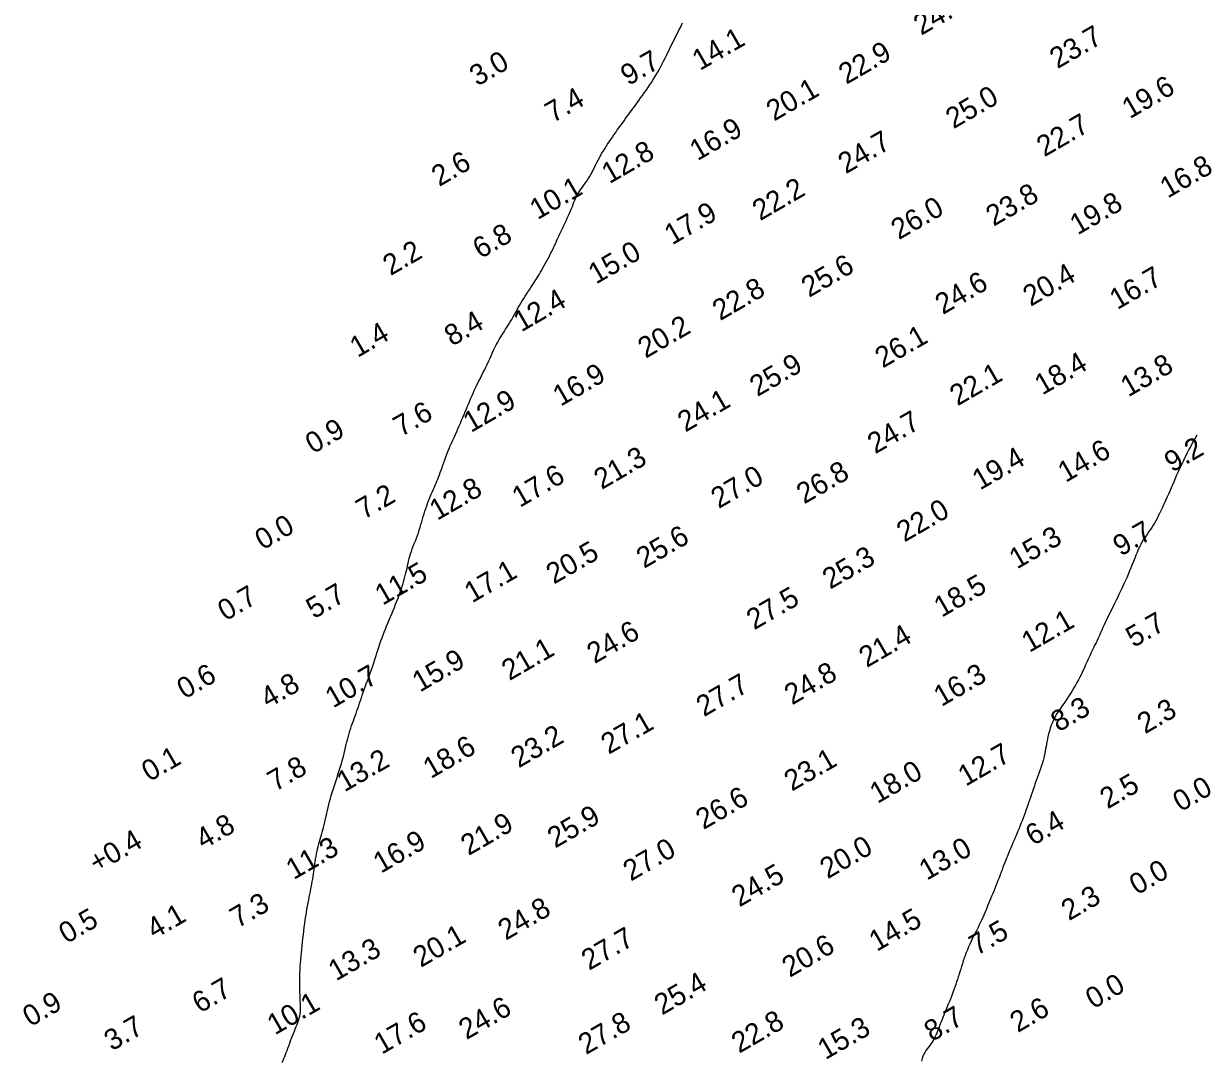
# Model space of a CAD drawing. Extents: x 3024098 to 3056816, y 418252 to 509144.
# Drawn here: x 3027143.2 to 3027426.2, y 424091.9 to 424342.2 of the extents above; entities that cross this region are included whole.
import ezdxf

# ---------------------------------------------------------------- set-up
doc = ezdxf.new("R2010")
doc.units = 0
doc.layers.add('V-CHAN-CONT-EL10', color=7, linetype='Continuous')
doc.layers.add('V-TOPO-SOUN-0911', color=7, linetype='Continuous')

msp = doc.modelspace()

# ---------------------------------------------------------------- linework, layer by layer
at = {"layer": 'V-CHAN-CONT-EL10'}
for points in [[(3027205.67, 424091.47), (3027205.86, 424091.95), (3027206.06, 424092.42), (3027206.25, 424092.9), (3027206.44, 424093.38), (3027206.63, 424093.88), (3027206.83, 424094.39), (3027207.04, 424094.94), (3027207.25, 424095.51), (3027207.47, 424096.1), (3027207.69, 424096.7), (3027207.91, 424097.3), (3027208.14, 424097.9), (3027208.37, 424098.48), (3027208.59, 424099.05), (3027208.81, 424099.59), (3027209.03, 424100.12), (3027209.24, 424100.63), (3027209.43, 424101.13), (3027209.6, 424101.64), (3027209.75, 424102.15), (3027209.88, 424102.67), (3027209.97, 424103.21), (3027210.03, 424103.78), (3027210.06, 424104.37), (3027210.06, 424104.99), (3027210.05, 424105.62), (3027210.02, 424106.28), (3027209.99, 424106.97), (3027209.95, 424107.67), (3027209.92, 424108.38), (3027209.89, 424109.12), (3027209.88, 424109.87), (3027209.87, 424110.64), (3027209.88, 424111.42), (3027209.89, 424112.21), (3027209.92, 424113.01), (3027209.95, 424113.81), (3027210, 424114.63), (3027210.05, 424115.45), (3027210.12, 424116.27), (3027210.19, 424117.1), (3027210.27, 424117.94), (3027210.36, 424118.79), (3027210.45, 424119.65), (3027210.55, 424120.52), (3027210.65, 424121.4), (3027210.76, 424122.3), (3027210.87, 424123.2), (3027210.98, 424124.1), (3027211.1, 424125), (3027211.22, 424125.89), (3027211.35, 424126.76), (3027211.48, 424127.61), (3027211.61, 424128.43), (3027211.75, 424129.22), (3027211.89, 424129.97), (3027212.04, 424130.7), (3027212.18, 424131.4), (3027212.32, 424132.07), (3027212.46, 424132.72), (3027212.58, 424133.36), (3027212.7, 424133.98), (3027212.81, 424134.58), (3027212.91, 424135.18), (3027213, 424135.77), (3027213.09, 424136.35), (3027213.17, 424136.93), (3027213.25, 424137.52), (3027213.34, 424138.11), (3027213.42, 424138.71), (3027213.51, 424139.32), (3027213.61, 424139.94), (3027213.71, 424140.56), (3027213.82, 424141.18), (3027213.94, 424141.8), (3027214.06, 424142.42), (3027214.19, 424143.02), (3027214.33, 424143.62), (3027214.48, 424144.19), (3027214.64, 424144.76), (3027214.8, 424145.32), (3027214.97, 424145.88), (3027215.14, 424146.44), (3027215.31, 424147.01), (3027215.47, 424147.6), (3027215.63, 424148.21), (3027215.79, 424148.85), (3027215.94, 424149.51), (3027216.09, 424150.19), (3027216.24, 424150.88), (3027216.4, 424151.59), (3027216.55, 424152.3), (3027216.72, 424153.02), (3027216.9, 424153.75), (3027217.08, 424154.47), (3027217.28, 424155.19), (3027217.49, 424155.9), (3027217.71, 424156.62), (3027217.93, 424157.34), (3027218.16, 424158.06), (3027218.4, 424158.78), (3027218.63, 424159.49), (3027218.87, 424160.21), (3027219.11, 424160.93), (3027219.34, 424161.66), (3027219.58, 424162.38), (3027219.8, 424163.11), (3027220.02, 424163.83), (3027220.23, 424164.56), (3027220.43, 424165.29), (3027220.61, 424166.01), (3027220.79, 424166.74), (3027220.95, 424167.46), (3027221.12, 424168.17), (3027221.28, 424168.87), (3027221.45, 424169.56), (3027221.62, 424170.23), (3027221.8, 424170.89), (3027221.99, 424171.52), (3027222.19, 424172.14), (3027222.4, 424172.75), (3027222.62, 424173.34), (3027222.83, 424173.93), (3027223.05, 424174.51), (3027223.27, 424175.1), (3027223.48, 424175.69), (3027223.69, 424176.29), (3027223.9, 424176.9), (3027224.11, 424177.52), (3027224.32, 424178.15), (3027224.53, 424178.79), (3027224.74, 424179.43), (3027224.96, 424180.09), (3027225.19, 424180.75), (3027225.43, 424181.43), (3027225.68, 424182.12), (3027225.94, 424182.81), (3027226.2, 424183.52), (3027226.46, 424184.23), (3027226.72, 424184.95), (3027226.98, 424185.68), (3027227.24, 424186.43), (3027227.49, 424187.17), (3027227.74, 424187.93), (3027227.99, 424188.69), (3027228.23, 424189.45), (3027228.48, 424190.21), (3027228.72, 424190.96), (3027228.97, 424191.71), (3027229.22, 424192.45), (3027229.48, 424193.18), (3027229.73, 424193.91), (3027230, 424194.62), (3027230.27, 424195.34), (3027230.55, 424196.06), (3027230.84, 424196.78), (3027231.13, 424197.51), (3027231.44, 424198.24), (3027231.75, 424198.99), (3027232.06, 424199.75), (3027232.38, 424200.51), (3027232.7, 424201.27), (3027233.01, 424202.03), (3027233.31, 424202.79), (3027233.61, 424203.54), (3027233.88, 424204.27), (3027234.14, 424204.99), (3027234.39, 424205.7), (3027234.61, 424206.4), (3027234.82, 424207.07), (3027235.02, 424207.73), (3027235.19, 424208.37), (3027235.35, 424209), (3027235.5, 424209.61), (3027235.64, 424210.2), (3027235.76, 424210.78), (3027235.88, 424211.35), (3027236, 424211.91), (3027236.13, 424212.47), (3027236.27, 424213.04), (3027236.42, 424213.61), (3027236.6, 424214.2), (3027236.8, 424214.8), (3027237.02, 424215.41), (3027237.26, 424216.04), (3027237.51, 424216.68), (3027237.77, 424217.33), (3027238.02, 424217.98), (3027238.27, 424218.63), (3027238.5, 424219.29), (3027238.72, 424219.95), (3027238.93, 424220.6), (3027239.12, 424221.25), (3027239.31, 424221.91), (3027239.49, 424222.55), (3027239.68, 424223.2), (3027239.87, 424223.84), (3027240.07, 424224.48), (3027240.28, 424225.12), (3027240.5, 424225.75), (3027240.73, 424226.38), (3027240.97, 424226.99), (3027241.2, 424227.59), (3027241.44, 424228.17), (3027241.68, 424228.73), (3027241.91, 424229.27), (3027242.13, 424229.78), (3027242.35, 424230.28), (3027242.57, 424230.77), (3027242.78, 424231.25), (3027242.98, 424231.73), (3027243.19, 424232.22), (3027243.39, 424232.73), (3027243.59, 424233.26), (3027243.79, 424233.81), (3027243.99, 424234.39), (3027244.2, 424235), (3027244.41, 424235.62), (3027244.62, 424236.26), (3027244.85, 424236.91), (3027245.09, 424237.57), (3027245.35, 424238.23), (3027245.62, 424238.9), (3027245.9, 424239.58), (3027246.19, 424240.25), (3027246.5, 424240.93), (3027246.81, 424241.62), (3027247.12, 424242.3), (3027247.43, 424242.99), (3027247.74, 424243.68), (3027248.05, 424244.37), (3027248.35, 424245.06), (3027248.65, 424245.75), (3027248.94, 424246.44), (3027249.24, 424247.12), (3027249.52, 424247.81), (3027249.81, 424248.48), (3027250.09, 424249.15), (3027250.36, 424249.82), (3027250.64, 424250.47), (3027250.91, 424251.13), (3027251.19, 424251.78), (3027251.47, 424252.43), (3027251.76, 424253.09), (3027252.06, 424253.75), (3027252.37, 424254.41), (3027252.7, 424255.09), (3027253.03, 424255.77), (3027253.37, 424256.46), (3027253.72, 424257.15), (3027254.07, 424257.84), (3027254.41, 424258.53), (3027254.75, 424259.23), (3027255.08, 424259.92), (3027255.4, 424260.6), (3027255.72, 424261.29), (3027256.02, 424261.97), (3027256.33, 424262.64), (3027256.64, 424263.31), (3027256.96, 424263.97), (3027257.29, 424264.63), (3027257.64, 424265.28), (3027258, 424265.92), (3027258.38, 424266.55), (3027258.77, 424267.18), (3027259.16, 424267.79), (3027259.55, 424268.41), (3027259.94, 424269.01), (3027260.31, 424269.6), (3027260.68, 424270.19), (3027261.02, 424270.77), (3027261.35, 424271.35), (3027261.68, 424271.92), (3027261.99, 424272.48), (3027262.29, 424273.04), (3027262.6, 424273.6), (3027262.92, 424274.15), (3027263.23, 424274.71), (3027263.57, 424275.26), (3027263.9, 424275.8), (3027264.25, 424276.35), (3027264.59, 424276.88), (3027264.94, 424277.41), (3027265.28, 424277.92), (3027265.61, 424278.43), (3027265.94, 424278.92), (3027266.25, 424279.39), (3027266.54, 424279.85), (3027266.84, 424280.31), (3027267.12, 424280.76), (3027267.4, 424281.22), (3027267.69, 424281.69), (3027267.97, 424282.17), (3027268.26, 424282.67), (3027268.56, 424283.2), (3027268.87, 424283.74), (3027269.17, 424284.3), (3027269.48, 424284.87), (3027269.79, 424285.46), (3027270.1, 424286.05), (3027270.4, 424286.64), (3027270.7, 424287.24), (3027270.98, 424287.83), (3027271.27, 424288.42), (3027271.54, 424289.02), (3027271.82, 424289.61), (3027272.09, 424290.21), (3027272.37, 424290.81), (3027272.65, 424291.42), (3027272.94, 424292.04), (3027273.23, 424292.67), (3027273.53, 424293.3), (3027273.83, 424293.93), (3027274.13, 424294.56), (3027274.42, 424295.19), (3027274.7, 424295.8), (3027274.97, 424296.39), (3027275.21, 424296.96), (3027275.44, 424297.51), (3027275.64, 424298.03), (3027275.84, 424298.54), (3027276.03, 424299.03), (3027276.22, 424299.5), (3027276.43, 424299.97), (3027276.65, 424300.42), (3027276.89, 424300.87), (3027277.16, 424301.32), (3027277.46, 424301.78), (3027277.77, 424302.23), (3027278.1, 424302.69), (3027278.43, 424303.17), (3027278.77, 424303.65), (3027279.11, 424304.14), (3027279.44, 424304.66), (3027279.76, 424305.19), (3027280.07, 424305.73), (3027280.38, 424306.29), (3027280.67, 424306.86), (3027280.97, 424307.43), (3027281.26, 424308.01), (3027281.56, 424308.59), (3027281.86, 424309.16), (3027282.16, 424309.73), (3027282.47, 424310.29), (3027282.79, 424310.84), (3027283.12, 424311.4), (3027283.45, 424311.95), (3027283.79, 424312.5), (3027284.15, 424313.06), (3027284.52, 424313.62), (3027284.9, 424314.19), (3027285.29, 424314.76), (3027285.68, 424315.33), (3027286.09, 424315.9), (3027286.49, 424316.47), (3027286.9, 424317.04), (3027287.31, 424317.6), (3027287.71, 424318.15), (3027288.1, 424318.7), (3027288.49, 424319.24), (3027288.88, 424319.77), (3027289.27, 424320.31), (3027289.65, 424320.84), (3027290.04, 424321.38), (3027290.44, 424321.92), (3027290.85, 424322.48), (3027291.26, 424323.04), (3027291.68, 424323.61), (3027292.11, 424324.19), (3027292.54, 424324.79), (3027292.97, 424325.4), (3027293.41, 424326.02), (3027293.84, 424326.65), (3027294.27, 424327.29), (3027294.7, 424327.94), (3027295.12, 424328.61), (3027295.54, 424329.28), (3027295.94, 424329.95), (3027296.33, 424330.62), (3027296.71, 424331.28), (3027297.07, 424331.94), (3027297.41, 424332.58), (3027297.74, 424333.21), (3027298.05, 424333.82), (3027298.35, 424334.42), (3027298.63, 424335.02), (3027298.91, 424335.6), (3027299.19, 424336.18), (3027299.46, 424336.75), (3027299.74, 424337.32), (3027300.02, 424337.89), (3027300.3, 424338.46), (3027300.58, 424339.03), (3027300.87, 424339.59), (3027301.15, 424340.14), (3027301.42, 424340.69), (3027301.69, 424341.23), (3027301.95, 424341.77), (3027302.2, 424342.29)], [(3027426.26, 424242.8), (3027425.87, 424242.13), (3027425.48, 424241.45), (3027425.1, 424240.76), (3027424.72, 424240.05), (3027424.34, 424239.34), (3027423.97, 424238.61), (3027423.6, 424237.86), (3027423.23, 424237.11), (3027422.86, 424236.34), (3027422.49, 424235.55), (3027422.13, 424234.76), (3027421.77, 424233.97), (3027421.41, 424233.18), (3027421.06, 424232.39), (3027420.72, 424231.61), (3027420.38, 424230.84), (3027420.05, 424230.09), (3027419.73, 424229.35), (3027419.41, 424228.62), (3027419.1, 424227.92), (3027418.79, 424227.22), (3027418.49, 424226.54), (3027418.19, 424225.88), (3027417.88, 424225.23), (3027417.58, 424224.59), (3027417.28, 424223.96), (3027416.98, 424223.35), (3027416.67, 424222.76), (3027416.36, 424222.18), (3027416.04, 424221.62), (3027415.72, 424221.08), (3027415.4, 424220.56), (3027415.06, 424220.05), (3027414.72, 424219.55), (3027414.38, 424219.06), (3027414.04, 424218.57), (3027413.7, 424218.07), (3027413.37, 424217.55), (3027413.04, 424217.01), (3027412.73, 424216.45), (3027412.43, 424215.84), (3027412.14, 424215.21), (3027411.85, 424214.54), (3027411.57, 424213.85), (3027411.29, 424213.13), (3027411, 424212.39), (3027410.69, 424211.63), (3027410.38, 424210.85), (3027410.06, 424210.06), (3027409.71, 424209.25), (3027409.36, 424208.44), (3027409, 424207.63), (3027408.62, 424206.81), (3027408.25, 424206), (3027407.87, 424205.2), (3027407.48, 424204.4), (3027407.1, 424203.62), (3027406.73, 424202.85), (3027406.35, 424202.09), (3027405.98, 424201.35), (3027405.62, 424200.61), (3027405.27, 424199.89), (3027404.92, 424199.17), (3027404.58, 424198.47), (3027404.25, 424197.77), (3027403.94, 424197.09), (3027403.63, 424196.41), (3027403.33, 424195.75), (3027403.04, 424195.11), (3027402.76, 424194.49), (3027402.49, 424193.88), (3027402.22, 424193.3), (3027401.96, 424192.75), (3027401.71, 424192.21), (3027401.46, 424191.7), (3027401.21, 424191.19), (3027400.98, 424190.7), (3027400.74, 424190.21), (3027400.51, 424189.73), (3027400.29, 424189.24), (3027400.06, 424188.76), (3027399.84, 424188.26), (3027399.61, 424187.76), (3027399.38, 424187.24), (3027399.14, 424186.71), (3027398.89, 424186.17), (3027398.62, 424185.6), (3027398.34, 424185.03), (3027398.04, 424184.42), (3027397.72, 424183.8), (3027397.37, 424183.17), (3027397.01, 424182.51), (3027396.62, 424181.85), (3027396.22, 424181.18), (3027395.79, 424180.5), (3027395.35, 424179.81), (3027394.88, 424179.12), (3027394.4, 424178.43), (3027393.92, 424177.74), (3027393.44, 424177.05), (3027392.98, 424176.35), (3027392.53, 424175.65), (3027392.12, 424174.95), (3027391.75, 424174.25), (3027391.43, 424173.54), (3027391.15, 424172.84), (3027390.91, 424172.14), (3027390.7, 424171.45), (3027390.52, 424170.77), (3027390.37, 424170.11), (3027390.24, 424169.47), (3027390.12, 424168.85), (3027390.01, 424168.26), (3027389.91, 424167.69), (3027389.81, 424167.14), (3027389.7, 424166.59), (3027389.59, 424166.05), (3027389.48, 424165.5), (3027389.34, 424164.94), (3027389.19, 424164.37), (3027389.01, 424163.78), (3027388.82, 424163.16), (3027388.61, 424162.53), (3027388.39, 424161.89), (3027388.16, 424161.23), (3027387.93, 424160.58), (3027387.69, 424159.91), (3027387.45, 424159.25), (3027387.22, 424158.6), (3027387, 424157.94), (3027386.77, 424157.3), (3027386.55, 424156.65), (3027386.33, 424156.01), (3027386.12, 424155.38), (3027385.9, 424154.75), (3027385.69, 424154.13), (3027385.48, 424153.52), (3027385.27, 424152.9), (3027385.05, 424152.29), (3027384.83, 424151.67), (3027384.6, 424151.05), (3027384.36, 424150.42), (3027384.12, 424149.78), (3027383.86, 424149.12), (3027383.59, 424148.45), (3027383.31, 424147.77), (3027383.03, 424147.09), (3027382.74, 424146.4), (3027382.46, 424145.73), (3027382.18, 424145.08), (3027381.92, 424144.45), (3027381.66, 424143.86), (3027381.42, 424143.3), (3027381.2, 424142.77), (3027380.99, 424142.27), (3027380.78, 424141.77), (3027380.58, 424141.28), (3027380.38, 424140.79), (3027380.17, 424140.28), (3027379.97, 424139.75), (3027379.75, 424139.18), (3027379.52, 424138.6), (3027379.29, 424137.98), (3027379.06, 424137.36), (3027378.81, 424136.71), (3027378.56, 424136.06), (3027378.31, 424135.41), (3027378.06, 424134.76), (3027377.8, 424134.11), (3027377.54, 424133.47), (3027377.29, 424132.83), (3027377.03, 424132.21), (3027376.78, 424131.59), (3027376.53, 424130.99), (3027376.29, 424130.39), (3027376.05, 424129.81), (3027375.82, 424129.25), (3027375.6, 424128.69), (3027375.37, 424128.14), (3027375.14, 424127.59), (3027374.9, 424127.03), (3027374.66, 424126.47), (3027374.4, 424125.9), (3027374.12, 424125.31), (3027373.81, 424124.7), (3027373.5, 424124.07), (3027373.17, 424123.43), (3027372.83, 424122.77), (3027372.49, 424122.1), (3027372.16, 424121.43), (3027371.83, 424120.75), (3027371.52, 424120.06), (3027371.22, 424119.37), (3027370.93, 424118.68), (3027370.67, 424118), (3027370.41, 424117.32), (3027370.17, 424116.64), (3027369.94, 424115.97), (3027369.73, 424115.31), (3027369.52, 424114.66), (3027369.32, 424114.02), (3027369.12, 424113.38), (3027368.93, 424112.76), (3027368.73, 424112.14), (3027368.54, 424111.52), (3027368.33, 424110.9), (3027368.12, 424110.27), (3027367.9, 424109.63), (3027367.67, 424108.98), (3027367.42, 424108.33), (3027367.17, 424107.67), (3027366.92, 424107.02), (3027366.66, 424106.37), (3027366.4, 424105.74), (3027366.15, 424105.12), (3027365.9, 424104.52), (3027365.67, 424103.94), (3027365.44, 424103.39), (3027365.22, 424102.85), (3027365.01, 424102.33), (3027364.81, 424101.82), (3027364.6, 424101.31), (3027364.4, 424100.8), (3027364.21, 424100.29), (3027364.01, 424099.78), (3027363.81, 424099.27), (3027363.61, 424098.76), (3027363.4, 424098.25), (3027363.17, 424097.76), (3027362.94, 424097.27), (3027362.69, 424096.81), (3027362.42, 424096.37), (3027362.14, 424095.95), (3027361.84, 424095.55), (3027361.53, 424095.16), (3027361.23, 424094.76), (3027360.93, 424094.35), (3027360.66, 424093.92), (3027360.4, 424093.46), (3027360.18, 424092.96), (3027359.99, 424092.41), (3027359.83, 424091.81)]]:
    msp.add_lwpolyline(points, dxfattribs=at)

# ---------------------------------------------------------------- texts
at = {"layer": 'V-TOPO-SOUN-0911'}
for s, p in [('24.8 ', (3027359.81, 424339.2)), ('14.1 ', (3027306.41, 424330.69)), ('23.7 ', (3027392.65, 424331.13)), ('3.0', (3027252.71, 424326.9)), ('9.7', (3027289.14, 424327.04)), ('22.9 ', (3027341.73, 424327.36)), ('19.6 ', (3027410.1, 424319.06)), ('7.4', (3027270.93, 424318.08)), ('20.1 ', (3027324.29, 424318.48)), ('25.0 ', (3027367.57, 424316.63)), ('16.9 ', (3027305.81, 424308.92)), ('22.7 ', (3027389.5, 424309.87)), ('24.7 ', (3027341.6, 424305.77)), ('12.8 ', (3027284.58, 424303.38)), ('2.6', (3027243.53, 424302.7)), ('16.8 ', (3027419.26, 424299.9)), ('10.1 ', (3027267.24, 424294.7)), ('22.2 ', (3027320.93, 424294.45)), ('23.8 ', (3027377.26, 424293.11)), ('19.8 ', (3027397.51, 424291.01)), ('17.9 ', (3027299.7, 424288.61)), ('26.0 ', (3027354.38, 424289.86)), ('6.8', (3027253.48, 424285.27)), ('2.2', (3027231.79, 424281.2)), ('15.0 ', (3027281.35, 424279.16)), ('25.6 ', (3027332.74, 424275.95)), ('20.4 ', (3027386.19, 424273.78)), ('24.6 ', (3027365.02, 424271.82)), ('16.7 ', (3027407.09, 424273)), ('22.8 ', (3027311.29, 424270.34)), ('12.4 ', (3027263.32, 424267.61)), ('8.4', (3027246.62, 424264.18)), ('1.4', (3027223.82, 424261.45)), ('20.2 ', (3027293.31, 424261.25)), ('26.1 ', (3027350.51, 424258.9)), ('25.9 ', (3027320.28, 424252.03)), ('18.4 ', (3027389.01, 424252.39)), ('13.8 ', (3027409.74, 424251.93)), ('16.9 ', (3027272.8, 424249.67)), ('22.1 ', (3027368.55, 424249.78)), ('12.9 ', (3027251.18, 424243.34)), ('24.1 ', (3027302.9, 424243.45)), ('7.6', (3027234.32, 424242.33)), ('24.7 ', (3027348.69, 424238.19)), ('0.9', (3027213.09, 424238.22)), ('14.6 ', (3027394.62, 424231.3)), ('9.2', (3027420.31, 424233.73)), ('21.3 ', (3027282.71, 424229.59)), ('19.4 ', (3027373.98, 424229.46)), ('26.8 ', (3027331.56, 424226.11)), ('17.6 ', (3027262.96, 424225.26)), ('27.0 ', (3027310.94, 424225)), ('7.2', (3027225.33, 424222.38)), ('12.8 ', (3027243.04, 424222.14)), ('22.0 ', (3027355.73, 424216.92)), (' 0.0 ', (3027199.33, 424214.07)), ('9.7', (3027407.91, 424213.49)), ('25.6 ', (3027292.94, 424210.57)), ('15.3 ', (3027382.87, 424210.4)), ('20.5 ', (3027271.18, 424206.76)), ('25.3 ', (3027337.83, 424205.54)), ('11.5 ', (3027229.88, 424201.67)), ('17.1 ', (3027251.46, 424202.24)), ('18.5 ', (3027364.72, 424198.75)), ('0.7', (3027191.96, 424197.87)), ('5.7', (3027213.29, 424198.4)), ('27.5 ', (3027319.51, 424195.73)), ('12.1 ', (3027385.87, 424190.27)), ('5.7', (3027411.02, 424191.47)), ('24.6 ', (3027281, 424187.57)), ('21.4 ', (3027346.65, 424186.64)), ('21.1 ', (3027260.45, 424183.48)), ('15.9 ', (3027238.88, 424180.71)), ('24.8 ', (3027328.64, 424177.62)), ('0.6', (3027182.12, 424179.04)), ('4.8', (3027202.26, 424176.84)), ('10.7 ', (3027217.91, 424176.87)), ('27.7 ', (3027307.38, 424174.77)), ('16.3 ', (3027364.67, 424177.23)), ('8.3', (3027392.91, 424171.1)), ('2.3', (3027413.78, 424170.64)), ('27.1 ', (3027284.4, 424165.69)), ('23.2 ', (3027262.7, 424162.43)), ('18.6 ', (3027241.5, 424159.84)), ('12.7 ', (3027370.54, 424158)), ('0.1', (3027173.6, 424159.11)), ('7.8', (3027203.97, 424156.76)), ('13.2 ', (3027220.67, 424156.62)), ('23.1 ', (3027328.59, 424156.8)), ('18.0 ', (3027349.23, 424153.83)), ('2.5', (3027404.75, 424152.53)), (' 0.0 ', (3027420.75, 424150.91)), ('26.6 ', (3027307.28, 424147.54)), ('4.8', (3027186.65, 424142.79)), ('21.9 ', (3027250.59, 424141.27)), ('25.9 ', (3027271.49, 424143.07)), ('6.4', (3027386.78, 424143.67)), ('+0.4 ', (3027160.89, 424137.07)), ('11.3 ', (3027208.43, 424135.46)), ('16.9 ', (3027229.46, 424137)), ('27.0 ', (3027289.75, 424135.1)), ('20.0 ', (3027337.22, 424135.66)), ('13.0 ', (3027361.14, 424135.3)), (' 0.0 ', (3027410.25, 424130.84)), ('24.5 ', (3027315.93, 424128.87)), ('7.3', (3027194.91, 424123.79)), ('2.3', (3027395.44, 424125.56)), ('0.5', (3027153.63, 424120.02)), ('4.1', (3027174.82, 424121.15)), ('24.8 ', (3027259.58, 424120.83)), ('14.5 ', (3027349.07, 424118.14)), ('7.5', (3027373.22, 424117.16)), ('20.1 ', (3027239.09, 424114.28)), ('27.7 ', (3027279.69, 424113.58)), ('13.3 ', (3027218.64, 424111.02)), ('20.6 ', (3027328.08, 424111.88)), ('6.7', (3027185.79, 424103.25)), ('25.4 ', (3027297.28, 424102.79)), (' 0.0 ', (3027399.69, 424103.34)), ('0.9', (3027144.91, 424099.97)), ('10.1 ', (3027203.89, 424097.98)), ('24.6 ', (3027250.1, 424096.85)), ('2.6', (3027383.07, 424098.57)), ('3.7', (3027164.57, 424094.13)), ('17.6 ', (3027229.66, 424093.31)), ('27.8 ', (3027278.94, 424093.24)), ('22.8 ', (3027315.88, 424093.57)), ('8.7', (3027362.37, 424096.39)), ('15.3 ', (3027336.68, 424092.02))]:
    msp.add_text(s, height=5, rotation=30, dxfattribs=at).set_placement(p)

doc.saveas('drawing.dxf')
